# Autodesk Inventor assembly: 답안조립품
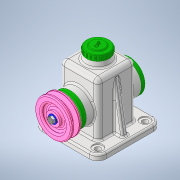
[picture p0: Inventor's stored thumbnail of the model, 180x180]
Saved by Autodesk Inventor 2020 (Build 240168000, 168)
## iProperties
Created: 2021-07
Part Number: 답안조립품
Document SubType Name: Assembly
Designer: Owner
Author: Owner
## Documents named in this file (14)
- C:\Users\Owner\Desktop\710715V1008\답안조립품.iam
- C:\Users\Owner\Desktop\710715V1008\본체.ipt
- C:\Users\Owner\Desktop\710715V1008\V-벨트풀리.ipt
- C:\Users\Owner\Desktop\710715V1008\뒤커버.ipt
- C:\Users\Owner\Desktop\710715V1008\멈춤링 15 x 1.ipt
- C:\Users\Owner\Desktop\710715V1008\베어링 15 x 35 x 11.ipt
- C:\Users\Owner\Desktop\710715V1008\볼트 M4 x 10.ipt
- C:\Users\Owner\Desktop\710715V1008\볼트 M6 x 12.ipt
- C:\Users\Owner\Desktop\710715V1008\상부캡.ipt
- C:\Users\Owner\Desktop\710715V1008\앞커버.ipt
- C:\Users\Owner\Desktop\710715V1008\오일실 15 25 7.ipt
- C:\Users\Owner\Desktop\710715V1008\와셔.ipt
- C:\Users\Owner\Desktop\710715V1008\축.ipt
- C:\Users\Owner\Desktop\710715V1008\키 5 x 5 x 14.ipt
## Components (1 placed, 1 different names)
1. V-벨트풀리:1
